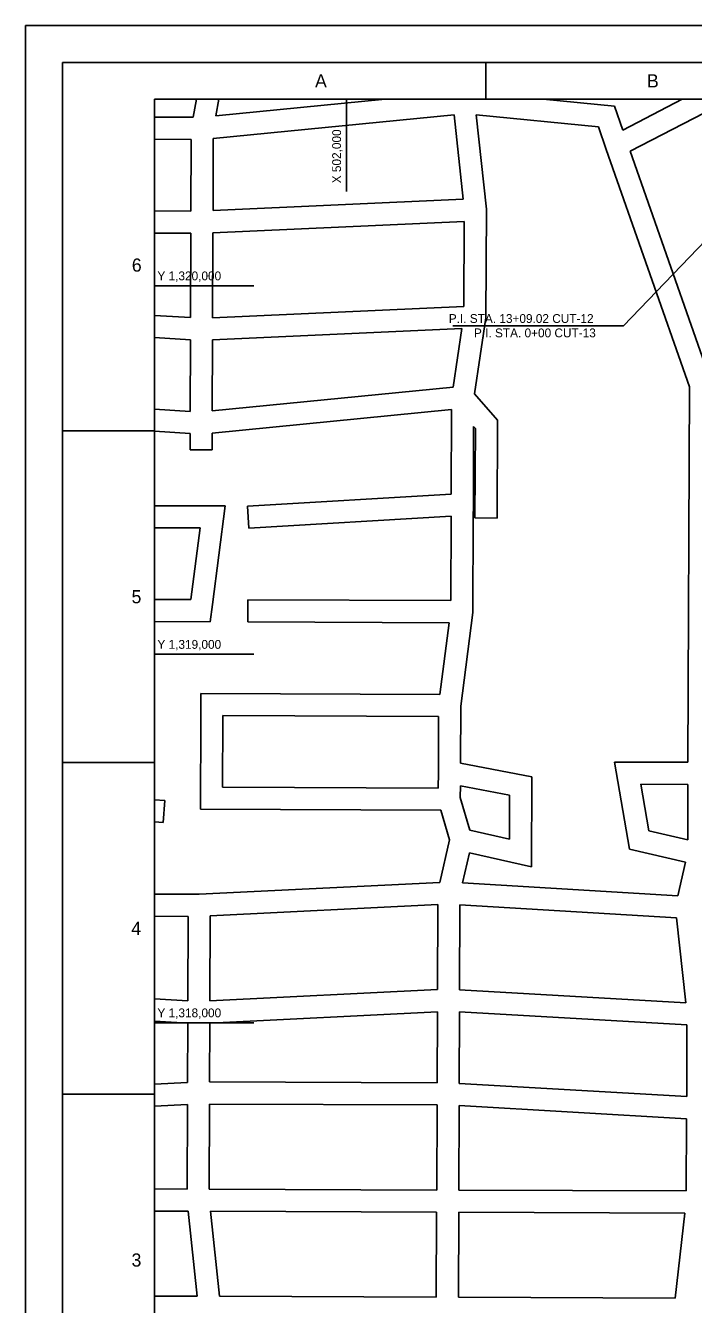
# Model space of a CAD drawing. Extents: x 501128 to 509328, y 1314906 to 1320706.
# Drawn here: x 501128 to 502942, y 1317236 to 1320706 of the extents above; entities that cross this region are included whole.
import ezdxf

# ---------------------------------------------------------------- set-up
doc = ezdxf.new("R2010")
doc.units = 0
for name, color, linetype in [('G-ANNO-TTLB', 7, 'Continuous'), ('Level 2', 7, 'Continuous'), ('Level 3', 7, 'Continuous'), ('Level 32', 7, 'Continuous'), ('Level 56', 7, 'Continuous')]:
    doc.layers.add(name, color=color, linetype=linetype)

msp = doc.modelspace()

# ---------------------------------------------------------------- linework, layer by layer
at = {"layer": 'G-ANNO-TTLB'}
for p, q in [((501228.1, 1320606.3), (501228.1, 1315006.3)), ((509228.1, 1320606.3), (501228.1, 1320606.3)), ((502378.1, 1320506.3), (502378.1, 1320606.3)), ((501478.1, 1315106.3), (501478.1, 1320506.3)), ((501478.1, 1320506.3), (509128.1, 1320506.3)), ((501478.1, 1319606.3), (501228.1, 1319606.3)), ((501478.1, 1318706.3), (501228.1, 1318706.3)), ((501478.1, 1317806.3), (501228.1, 1317806.3))]:
    msp.add_line(p, q, dxfattribs=at)
for points in [[(501128.1, 1314906.3), (509328.1, 1314906.3), (509328.1, 1320706.3), (501128.1, 1320706.3)], [(501128.1, 1314906.3), (509328.1, 1314906.3), (509328.1, 1320706.3), (501128.1, 1320706.3)], [(501128.1, 1320706.3), (509328.1, 1320706.3), (509328.1, 1314906.3), (501128.1, 1314906.3)]]:
    msp.add_lwpolyline(points, close=True, dxfattribs=at)
msp.add_lwpolyline([(501128.1, 1320656.3), (501128.1, 1320706.3), (501178.1, 1320706.3)], dxfattribs=at)
at = {"layer": 'Level 2'}
for p, q in [((502000, 1320256.3), (502000, 1320506.3)), ((501478.1, 1320000), (501748.1, 1320000)), ((501478.1, 1319000), (501748.1, 1319000)), ((501478.1, 1318000), (501748.1, 1318000))]:
    msp.add_line(p, q, dxfattribs=at)
at = {"layer": 'Level 3'}
msp.add_line((501478.1, 1320000), (501478.1, 1315106.3), dxfattribs=at)
at = {"layer": 'Level 32'}
for p, q in [((501583.2, 1320457.3), (501592.1, 1320506.3)), ((501644.8, 1320461), (501653.1, 1320506.3)), ((502105, 1320506.3), (501644.8, 1320461)), ((502727.9, 1320487.3), (502533.8, 1320506.3)), ((502750.5, 1320422.5), (502911.9, 1320506.3)), ((501583.2, 1320457.3), (501478.1, 1320457.8)), ((502292, 1320464.4), (501638.1, 1320400)), ((502316.6, 1320234.8), (502292, 1320464.4)), ((502683.9, 1320431.3), (502352.4, 1320463.7)), ((502379.8, 1320207.8), (502352.4, 1320463.7)), ((502750.5, 1320422.5), (502727.9, 1320487.3)), ((502770.6, 1320365.3), (502972, 1320469.9)), ((502705.3, 1320370.1), (502683.9, 1320431.3)), ((501578.1, 1320397.4), (501478.1, 1320397.8)), ((501577.3, 1320202.9), (501578.1, 1320397.4)), ((501637.3, 1320204.2), (501638.1, 1320400)), ((502316.6, 1320234.8), (501637.3, 1320204.2)), ((501577.3, 1320202.9), (501478.1, 1320203.3)), ((502378.7, 1319913.1), (502379.8, 1320207.8)), ((501577.1, 1320142.9), (501478.1, 1320143.3)), ((501636.2, 1319913.3), (501637.1, 1320144.1)), ((502319.7, 1320174.8), (501637.1, 1320144.1)), ((502318.8, 1319944.1), (502319.7, 1320174.8)), ((501576.2, 1319913.8), (501577.1, 1320142.9)), ((502318.8, 1319944.1), (501636.2, 1319913.3)), ((501576.2, 1319913.8), (501478.1, 1319919.7)), ((502347.3, 1319706.7), (502378.7, 1319913.1)), ((502313.5, 1319883.8), (501636, 1319853.2)), ((502289.4, 1319724.9), (502313.5, 1319883.8)), ((501576, 1319853.7), (501478.1, 1319859.6)), ((501575.2, 1319659.4), (501576, 1319853.7)), ((501635.2, 1319660.5), (501636, 1319853.2)), ((502289.4, 1319724.9), (501635.2, 1319660.5)), ((501575.2, 1319659.4), (501478.1, 1319665.5)), ((502285.4, 1319664.3), (501635, 1319600.2)), ((502284.5, 1319434.8), (502285.4, 1319664.3)), ((501575, 1319599.3), (501478.1, 1319605.4)), ((501574.8, 1319554.8), (501575, 1319599.3)), ((501634.8, 1319554.6), (501635, 1319600.2)), ((502344.4, 1319406.4), (502345.2, 1319618.3)), ((501574.8, 1319554.8), (501634.8, 1319554.6)), ((502284.5, 1319434.8), (501731.4, 1319402.4)), ((501604.2, 1319403), (501478.1, 1319403.4)), ((501670.5, 1319402.7), (501604.2, 1319403)), ((501635.5, 1319134.9), (501670.5, 1319402.7)), ((501735, 1319342.5), (501731.4, 1319402.4)), ((502344.3, 1319370.1), (502344.4, 1319406.4)), ((502284.3, 1319374.7), (501735, 1319342.5)), ((502283.4, 1319145.8), (502284.3, 1319370.3)), ((502284.3, 1319370.3), (502284.3, 1319374.7)), ((502343.3, 1319113.7), (502344.3, 1319370.1)), ((502348.8, 1319370), (502408.8, 1319369.8)), ((501602.2, 1319343), (501478.1, 1319343.4)), ((501576.8, 1319148.6), (501602.2, 1319343)), ((501576.8, 1319148.6), (501478.1, 1319149)), ((501732.1, 1319088), (501732.3, 1319148)), ((502283.4, 1319145.8), (501732.3, 1319148)), ((501629.4, 1319088.4), (501635.5, 1319134.9)), ((502310, 1318859.3), (502343.3, 1319113.7)), ((501629.4, 1319088.4), (501478.1, 1319089)), ((502279.1, 1319085.8), (501732.1, 1319088)), ((502253.7, 1318891.4), (502279.1, 1319085.8)), ((501604.2, 1318827.6), (501604.5, 1318894)), ((502253.7, 1318891.4), (501604.5, 1318894)), ((502309.4, 1318704.3), (502310, 1318859.3)), ((501603.2, 1318579.5), (501604.2, 1318827.6)), ((501663.5, 1318639.3), (501664.2, 1318827.4)), ((502249.9, 1318831.5), (501664.2, 1318833.7)), ((501664.2, 1318827.4), (501664.2, 1318833.7)), ((502249.3, 1318679.7), (502249.9, 1318831.5)), ((502502.9, 1318667.2), (502309.4, 1318704.3)), ((502768.9, 1318471), (502727.8, 1318707.8)), ((502927.3, 1318707), (502727.8, 1318707.8)), ((502249.1, 1318637), (502249.3, 1318679.7)), ((502502, 1318423.1), (502502.9, 1318667.2)), ((502249.1, 1318637), (501663.5, 1318639.3)), ((502309, 1318611.1), (502309.1, 1318643.3)), ((502442.7, 1318617.7), (502309.1, 1318643.3)), ((502442.3, 1318498.3), (502442.7, 1318617.7)), ((502821.2, 1318520.6), (502799.2, 1318647.5)), ((502927.1, 1318647), (502799.2, 1318647.5)), ((502926.5, 1318496.4), (502927.1, 1318647)), ((501506.1, 1318603.5), (501478.1, 1318605.3)), ((501502.1, 1318543.6), (501506.1, 1318603.5)), ((502334.7, 1318523), (502309, 1318611.1)), ((502256.5, 1318576.9), (501603.2, 1318579.5)), ((502279.9, 1318496.7), (502256.5, 1318576.9)), ((501502.1, 1318543.6), (501478.1, 1318545.2)), ((502442.3, 1318498.3), (502334.7, 1318523)), ((502926.5, 1318496.4), (502821.2, 1318520.6)), ((502253.8, 1318381.2), (502279.9, 1318496.7)), ((502315.1, 1318380.2), (502333.5, 1318461.7)), ((502502, 1318423.1), (502333.5, 1318461.7)), ((502920.5, 1318436.2), (502768.9, 1318471)), ((502899.9, 1318345), (502920.5, 1318436.2)), ((502253.8, 1318381.2), (501599.3, 1318348.7)), ((502899.9, 1318345), (502315.1, 1318380.2)), ((501599.3, 1318348.7), (501478.1, 1318349.1)), ((502247.9, 1318320.8), (501629.8, 1318290.1)), ((502247, 1318090.1), (502247.9, 1318320.8)), ((502307, 1318089.8), (502307.9, 1318320.5)), ((502896.4, 1318285.1), (502307.9, 1318320.5)), ((501569.8, 1318288.8), (501478.1, 1318289.1)), ((501568.9, 1318059.6), (501569.8, 1318288.8)), ((501628.9, 1318059.3), (501629.8, 1318290.1)), ((502921.1, 1318054.5), (502896.4, 1318285.1)), ((501568.9, 1318059.6), (501478.1, 1318064.8)), ((502247, 1318090.1), (501628.9, 1318059.3)), ((502921.1, 1318054.5), (502307, 1318089.8)), ((502246.8, 1318030), (501628.7, 1317999.3)), ((502246, 1317837.2), (502246.8, 1318030)), ((502306, 1317835.4), (502306.8, 1318029.8)), ((502924.6, 1317994.2), (502306.8, 1318029.8)), ((501568.7, 1317999.5), (501478.1, 1318004.7)), ((501568.1, 1317838.2), (501568.7, 1317999.5)), ((501628.1, 1317839.6), (501628.7, 1317999.3)), ((502923.8, 1317799.8), (502924.6, 1317994.2)), ((501568.1, 1317838.2), (501478.1, 1317833.8)), ((502246, 1317837.2), (501628.1, 1317839.6)), ((502923.8, 1317799.8), (502306, 1317835.4)), ((501567.8, 1317778.2), (501478.1, 1317773.7)), ((501566.9, 1317549), (501567.8, 1317778.2)), ((501626.9, 1317548.7), (501627.8, 1317779.6)), ((502245.8, 1317777.2), (501627.8, 1317779.6)), ((502244.9, 1317546.3), (502245.8, 1317777.2)), ((502304.9, 1317546.1), (502305.8, 1317775.3)), ((502923.6, 1317739.7), (502305.8, 1317775.3)), ((502922.8, 1317543.7), (502923.6, 1317739.7)), ((501566.9, 1317549), (501478.1, 1317549.3)), ((502244.9, 1317546.3), (501626.9, 1317548.7)), ((502922.8, 1317543.7), (502304.9, 1317546.1)), ((501569.8, 1317488.9), (501478.1, 1317489.3)), ((501594.6, 1317258), (501569.8, 1317488.9)), ((501654.9, 1317257.8), (501630.2, 1317488.7)), ((502244.6, 1317486.3), (501630.2, 1317488.7)), ((502243.7, 1317255.5), (502244.6, 1317486.3)), ((502303.7, 1317255.2), (502304.6, 1317486.1)), ((502919.1, 1317483.7), (502304.6, 1317486.1)), ((502892.5, 1317253), (502919.1, 1317483.7)), ((501594.6, 1317258), (501478.1, 1317258.5)), ((502243.7, 1317255.5), (501654.9, 1317257.8)), ((502892.5, 1317253), (502303.7, 1317255.2))]:
    msp.add_line(p, q, dxfattribs=at)
for points in [[(502927.3, 1318707), (502931.3, 1319726.2), (502705.4, 1320370)], [(502987.2, 1318676.8), (502991.3, 1319736.3), (502770.6, 1320365.3)], [(502408.8, 1319369.8), (502409.9, 1319635.7), (502347.3, 1319706.7)], [(502348.8, 1319370), (502349.8, 1319613.1), (502345.2, 1319618.3)]]:
    msp.add_lwpolyline(points, dxfattribs=at)
at = {"layer": 'Level 56'}
for p, q in [((503178.4, 1320334.8), (502752.4, 1319891.8)), ((502288.4, 1319891.8), (502752.4, 1319891.8)), ((502752.4, 1319891.8), (502406.7, 1319891.8))]:
    msp.add_line(p, q, dxfattribs=at)

# ---------------------------------------------------------------- texts
at = {"layer": 'G-ANNO-TTLB'}
for s, p in [('A', (501914.5, 1320538.5)), ('B', (502816.1, 1320538.5)), ('6', (501416.9, 1320038.5)), ('5', (501416.1, 1319138.5)), ('4', (501415.3, 1318238.5)), ('3', (501416.1, 1317338.5))]:
    msp.add_text(s, height=35.7, dxfattribs=at).set_placement(p)
at = {"layer": 'Level 3'}
msp.add_text('X 502,000', height=24, rotation=90, dxfattribs=at).set_placement((501985, 1320278.3))
for s, p in [('Y 1,320,000', (501486.3, 1320015)), ('Y 1,319,000', (501486.3, 1319015)), ('Y 1,318,000', (501486.3, 1318015))]:
    msp.add_text(s, height=24, dxfattribs=at).set_placement(p)
at = {"layer": 'Level 56'}
for s, p in [('P.I. STA. 13+09.02 CUT-12', (502277.7, 1319899.3)), ('P.I. STA. 0+00 CUT-13', (502346.1, 1319860.3))]:
    msp.add_text(s, height=24, dxfattribs=at).set_placement(p)

doc.saveas('drawing.dxf')
